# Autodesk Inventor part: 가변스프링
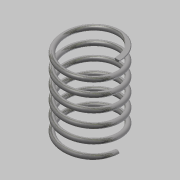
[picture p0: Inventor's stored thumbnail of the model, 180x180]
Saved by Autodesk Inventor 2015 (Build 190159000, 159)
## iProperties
Created: 2016-02
Part Number: 가변스프링
Material: 스테인레스 스틸
Document SubType Name: Modeling
Designer: Administrator
Density: 8 g/cm^3
Appearance: 반연마
Mass: 84.2117 g
Surface Area: 106.451 cm^2
Volume: 10.5265 cm^3
Author: Administrator
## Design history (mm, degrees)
sketch "스케치1"
  geometry: L1 (0, 0)-(-22.5, 0); L2 (-22.5, 0)-(-22.5, 67.25); L3 (-22.5, 67.25)-(0, 67.25); L4 (0, 67.25)-(0, 0); C1 r 2 at (-22.5, 0)
  constraints: 8 end point, 2 parallel, 1 centre point, 1 coincident, 1 horizontal, 1 perpendicular
  dimensions: "d0" = 45 diameter of L2 L4; "d1" = 67.25 distance between parallel lines of L1 L3 (derived); "d2" = 4 diameter of C1
feature "코일1" sketch "스케치1" pitch "d3" = 10; turns "d5" = 6; dims "d4" = 67.25 (= d1), "d6" = 0, angle "d7" = 90 deg, angle "d8" = 90 deg, "d9" = 0, "d10" = 0
node "작업 평면1"
sketch "스케치2"
  geometry: L1 (-24.5, 0)-(-20.5, 0) reference; 1 further point
  constraints: 1 horizontal alignment
extrude "돌출1" cut sketch "스케치2" stored distance "d11" = 10; taper "d12" = 0 deg
node "작업 평면2"
sketch "스케치4"
  geometry: L1 (-20.5, 0)-(-24.5, 0) reference; 1 further point
  constraints: 1 horizontal alignment
extrude "돌출2" cut sketch "스케치4" stored distance "d13" = 10; taper "d14" = 0 deg
node "솔리드1"
node "절단 모서리 투영1"
node "절단 모서리 투영2"
